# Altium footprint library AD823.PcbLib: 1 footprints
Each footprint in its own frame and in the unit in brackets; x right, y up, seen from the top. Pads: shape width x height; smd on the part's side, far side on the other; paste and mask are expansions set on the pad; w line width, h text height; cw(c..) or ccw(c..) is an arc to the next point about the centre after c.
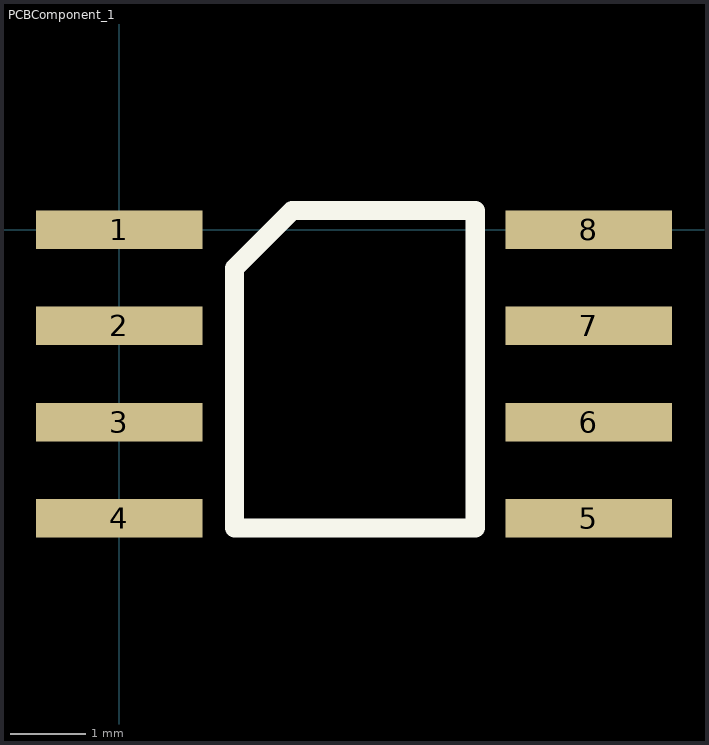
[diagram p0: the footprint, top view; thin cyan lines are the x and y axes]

## PCBComponent_1 [mm]
pads (8):
  rect 2.2x0.51 all layers, no hole: 1(0,0) 2(0,-1.27) 3(0,-2.54) 4(0,-3.81) 5(6.2,-3.81) 6(6.2,-2.54) 7(6.2,-1.27) 8(6.2,0)
Top Overlay:
  lines w0.254: 1.524,-3.937 1.524,-0.508 2.286,0.254 2.413,0.254 4.699,0.254 4.699,-3.937 1.524,-3.937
